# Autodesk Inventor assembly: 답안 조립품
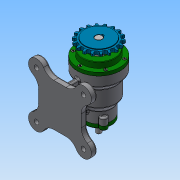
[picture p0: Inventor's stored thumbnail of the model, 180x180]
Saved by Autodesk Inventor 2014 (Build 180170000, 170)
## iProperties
Created: 2017-03
Part Number: 답안 조립품
Document SubType Name: Assembly
Designer: NET
Author: NET
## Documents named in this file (10)
- C:\Users\NET\Desktop\470307V1013\답안 조립품.iam
- C:\Users\NET\Desktop\470307V1013\답안부품.ipt
- C:\Users\NET\Desktop\470307V1013\축.ipt
- C:\Users\NET\Desktop\470307V1013\키5x5.ipt
- C:\Users\NET\Desktop\470307V1013\스프로킷.ipt
- C:\Users\NET\Desktop\470307V1013\앞커버.ipt
- C:\Users\NET\Desktop\470307V1013\볼트 M4 x 12.ipt
- C:\Users\NET\Desktop\470307V1013\뒤커버.ipt
- C:\Users\NET\Desktop\470307V1013\베어링-6203.ipt
- C:\Users\NET\Desktop\470307V1013\베어링-6200.ipt
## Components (9 placed, 1 different names)
1. ISO 4762 M4 x 12:1
2. ISO 4762 M4 x 12:2
3. ISO 4762 M4 x 12:3
4. ISO 4762 M4 x 12:4
5. ISO 4762 M4 x 12:5
6. ISO 4762 M4 x 12:6
7. ISO 4762 M4 x 12:7
8. ISO 4762 M4 x 12:8
9. ISO 4762 M4 x 12:9
